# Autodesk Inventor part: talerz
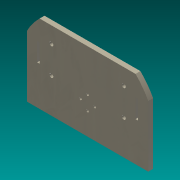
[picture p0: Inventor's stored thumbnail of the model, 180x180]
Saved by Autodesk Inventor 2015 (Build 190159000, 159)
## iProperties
Created: 2016-02
Part Number: talerz
Material: Generic
Document SubType Name: Modeling
Designer: Rafał
Density: 1 g/cm^3
Appearance: Light Beige
Author: Rafał
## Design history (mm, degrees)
sketch "Sketch1" dims "d1" = 14.5
  geometry: C1 r 70 at (0, 0); C2 r 1.25 at (0, 7.25); C3 r 1.25 at (-7.25, 0); C4 r 1.25 at (0, -7.25); C5 r 1.25 at (7.25, 0); 2 further points
  constraints: 5 centre point, 2 coincident, 1 vertical alignment, 11 other
  dimensions: "d0" = 140 diameter of C1; "d2" = 2.5 diameter of C2; "d5" = 360 deg dimension on point (0, 0) C2.centre (derived)
extrude "Extrusion1" new body sketch "Sketch1" distance "d7" = 5; taper "d8" = 0 deg
sketch "Sketch3"
  geometry: L1 (0, 0)-(0, 55); L2 (0, 55)-(43.301, 55); L3 (-43.301, 55)-(0, 55); A1 r 70 centre (0, 0) between (43.301, 55) and (-43.301, 55) reference
  constraints: 6 end point, 2 point on circle, 1 collinear, 1 perpendicular, 1 point on line, 1 vertical
  dimensions: "d11" = 55 distance of L1.start L1.end
extrude "Extrusion3" cut sketch "Sketch3" distance "d12" = 7; taper "d13" = 0 deg
sketch "Sketch4"
  geometry: L1 (43.301, 55)-(-43.301, 55) reference; L2 (0, 55)-(0, -66.946); L3 (51.5, -29)-(49, -29); L4 (49, -29)-(49, -10); L5 (49, -10)-(51.5, -10); L6 (51.5, -10)-(51.5, -29); L7 (0, 0)-(35.886, 0); L8 (51.5, -19.5)-(49, -19.5); L9 (-51.5, -10)-(-51.5, -29); L10 (-51.5, -29)-(-49, -29); L11 (-49, -29)-(-49, -10); L12 (-49, -10)-(-51.5, -10); L13 (0, 0)-(62, 0); L14 (62, 0)-(62, -32.496); L15 (62, 0)-(62, 32.496); L16 (-62, 0)-(-62, -32.496); L17 (-62, 0)-(-62, 32.496); L18 (62, -32.496)-(73.129, -32.496); L19 (73.129, -32.496)-(73.129, 32.496); L20 (73.129, 32.496)-(62, 32.496); L21 (62, 32.496)-(62, -32.496); L22 (-62, -32.496)-(-82.465, -32.496); L23 (-82.465, -32.496)-(-82.465, 35.893); L24 (-82.465, 35.893)-(-62, 35.893); L25 (-62, 35.893)-(-62, -32.496); C1 r 2 at (37, -33.5); C2 r 2 at (37, -5.5); C3 r 2 at (-37, -33.5); C4 r 2 at (-37, -5.5); A1 r 70 centre (0, 0) between (-43.301, 55) and (43.301, 55) reference; 1 further point
  constraints: 48 end point, 10 symmetric about line, 6 parallel, 5 horizontal, 5 perpendicular, 4 centre point, 3 midpoint, 2 point on circle, 2 point on line, 1 vertical, 3 other
  dimensions: "d14" = 2.5 distance of L4.end L5.end; "d15" = 19 distance of L3.end L4.end; "d16" = 49 distance between parallel lines of L2 L4; "d17" = 10 distance between parallel lines of L7 L5; "d18" = 4 diameter of C1; "d19" = 12 distance from line of C1.centre L4; "d20" = 4.5 distance from line of L3 C1.centre; "d23" = 4.5 distance from line of L5 C2.centre; "d24" = 62 distance of L7.start L13.end
extrude "Extrusion5" cut sketch "Sketch4" distance "d25" = 7; taper "d26" = 0 deg
sketch "Sketch6"
  geometry: L1 (0, 0)-(-21.864, 0); L2 (-21.864, 0)-(-21.864, 30); L3 (-21.864, 30)-(0, 30); L4 (0, 30)-(0, 0); L5 (0, 30)-(110.924, 30); L6 (110.924, 30)-(110.924, 74.677); L7 (110.924, 74.677)-(0, 74.677); L8 (0, 74.677)-(0, 30); L9 (0, 30)-(-83.451, 30); L10 (-83.451, 30)-(-83.451, 74.677); L11 (-83.451, 74.677)-(0, 74.677); L12 (0, 74.677)-(0, 30); L13 (0, 0)-(55.462, 0); L14 (55.462, 0)-(55.462, -50); L15 (55.462, -50)-(0, -50); L16 (0, -50)-(0, 0); L17 (0, -50)-(61.243, -50); L18 (61.243, -50)-(61.243, -72.003); L19 (61.243, -72.003)-(0, -72.003); L20 (0, -72.003)-(0, -50); L21 (0, -50)-(-67.424, -50); L22 (-67.424, -50)-(-67.424, -72.003); L23 (-67.424, -72.003)-(0, -72.003); L24 (0, -72.003)-(0, -50)
  constraints: 48 end point, 12 parallel, 6 horizontal, 6 perpendicular, 2 point on line
  dimensions: "d27" = 30 distance of L1.end L2.end; "d28" = 50 distance of L13.end L14.end
extrude "Extrusion6" cut sketch "Sketch6" distance "d29" = 10; taper "d30" = 0 deg
body "Solid1"
